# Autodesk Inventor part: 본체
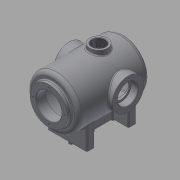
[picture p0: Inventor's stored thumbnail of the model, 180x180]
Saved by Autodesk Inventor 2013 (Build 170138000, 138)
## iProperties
Created: 2016-02
Part Number: 본체
Material: 일반
Document SubType Name: Modeling
Designer: mduedu
Density: 2.71 g/cm^3
Author: mduedu
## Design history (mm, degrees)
sketch "스케치2"
  geometry: L1 (0, 100)-(0, -100); L2 (65, -75.993)-(65, 100); L3 (65, 100)-(0, 100); A1 r 100 centre (0, 0) between (0, -100) and (65, -75.993); 2 further points
  constraints: 6 end point, 2 midpoint, 2 point on circle, 1 centre point, 1 coincident, 1 horizontal, 1 parallel, 1 vertical
  dimensions: "d3" = 200 distance of L1.start L1.end; "d5" = 130 diameter of L2 L1; "d6" = 100 radius of A1
revolve "회전1" sketch "스케치2" stored, may be unused: angle "d7" = 90 deg
sketch "스케치3"
  geometry: C1 r 47.5 at (0, 0); 1 further point
  constraints: 1 centre point, 1 coincident
  dimensions: "d8" = 95 diameter of C1
extrude "돌출2" join sketch "스케치3" distance "d10" = 10; taper "d11" = 0 deg
sketch "스케치5"
  geometry: L1 (47.5, 110)-(47.5, 100) reference; L2 (47.5, 100)-(65, 100) reference; L3 (65, 100)-(65, -75.993) reference; L4 (-65, -75.993)-(-65, 100) reference; L5 (-65, 100)-(-47.5, 100) reference; L6 (-47.5, 100)-(-47.5, 110) reference; L7 (-47.5, 110)-(47.5, 110) reference; L8 (55, 85)-(55, -71.239); L9 (0, 85)-(55, 85); L10 (0, 85)-(0, -90); A1 r 100 centre (0, 0) between (0, -100) and (65, -75.993) reference; A2 r 100 centre (0, 0) between (-65, -75.993) and (0, -100) reference; A3 r 90 centre (0, 0) between (0, -90) and (55, -71.239); 1 further point
  constraints: 6 end point, 2 point on circle, 1 centre point, 1 parallel, 1 perpendicular, 1 point on line, 1 vertical
  dimensions: "d13" = 10 distance between parallel lines of L3 L8; "d14" = 10 radial gap between concentric circles of A3 A1; "d15" = 15 distance between parallel lines of L9 L2
revolve "회전2" sketch "스케치5" stored, may be unused: angle "d16" = 90 deg
hole "구멍1" diameter "d19" = 65; stored, may be unused: countersink angle "d23" = 90 deg, drill point angle "d25" = 118 deg; dims "d17" = 10, "d18" = 10, "d20" = 6, "d21" = 4, "d22" = 2, "d24" = 8
node "작업 평면1"
sketch "스케치6"
  geometry: L1 (47.5, 110)-(-47.5, 110) reference; C1 r 40 at (0, -17); 1 further point
  constraints: 1 centre point, 1 vertical alignment
  dimensions: "d27" = 80 diameter of C1; "d29" = 127 distance from line of C1.centre L1
extrude "돌출3" join sketch "스케치6" stored distance "d30" = 10; taper "d31" = 0 deg
hole "구멍2" diameter "d34" = 42; stored, may be unused: countersink angle "d38" = 90 deg, drill point angle "d40" = 118 deg; dims "d32" = 10, "d33" = 10, "d35" = 6, "d36" = 52, "d37" = 18, "d39" = 8
sketch "스케치7" dims "d41" = 65
  geometry: C1 r 40 at (0, 0) reference; 3 further points
  constraints: 2 vertical alignment, 1 coincident, 2 other
hole "구멍3" sketch "스케치7" at (0, 32.5) diameter "d43" = 3.242; stored, may be unused: countersink angle "d47" = 90 deg, drill point angle "d49" = 118 deg; dims "d44" = 11, "d45" = 13, "d46" = 18, "d48" = 13
sketch "스케치8" dims "d53" = 80
  geometry: 3 further points
  constraints: 2 vertical alignment, 1 coincident, 2 other
hole "구멍4" sketch "스케치8" at (0, 40) diameter "d56" = 3.242; stored, may be unused: countersink angle "d60" = 90 deg, drill point angle "d62" = 118 deg; dims "d57" = 11, "d58" = 13, "d59" = 18, "d61" = 13
fillet "모깎기1" dims "d66" = 10
fillet "모깎기2" dims "d67" = 3
fillet "모깎기3" dims "d68" = 0.3
chamfer "모따기1" distance "d69" = 1; stored, may be unused: second distance "d70" = 2, angle "d71" = 45 deg
node "작업 평면5"
sketch "스케치10"
  geometry: L1 (-50, -63)-(50, -63); L2 (50, -63)-(50, -43); L3 (50, -43)-(-50, -43); L4 (-50, -43)-(-50, -63); L5 (-50, 0)-(50, 0); L6 (-50, 63)-(50, 63); L7 (50, 63)-(50, 43); L8 (50, 43)-(-50, 43); L9 (-50, 43)-(-50, 63); 2 further points
  constraints: 18 end point, 4 symmetric about line, 2 parallel, 2 perpendicular, 1 coincident, 1 horizontal, 1 midpoint
  dimensions: "d80" = 20 distance of L3.end L1.start; "d82" = 100 distance of L1.start L1.end; "d130" = 43 vertical distance of L3.end point (0, 0); "d131" = 50 horizontal distance of L3.end point (0, 0); "d132" = 100 distance of L5.start L5.end
extrude "돌출5" join sketch "스케치10" stored distance "d84" = 10; taper "d85" = 0 deg
sketch "스케치11"
  geometry: L1 (-100, -43)-(-100, 43); L2 (-65, 90)-(-65, -71.239) reference; L3 (-100, -43)-(-41.533, -43) reference; L4 (-100, 43)-(-41.533, 43) reference; 1 further point
  constraints: 2 end point, 1 point on line, 1 vertical
feature "리브1" sketch "스케치11" dims "d88" = 1, "d89" = 20, "d90" = 0, "d91" = 0, "d92" = 1, "d93" = 1
fillet "모깎기18" dims "d179" = 3
fillet "모깎기19" dims "d180" = 3
fillet "모깎기20" dims "d181" = 3
fillet "모깎기21" dims "d182" = 3
fillet "모깎기16" dims "d167" = 3
fillet "모깎기17" dims "d168" = 3
node "작업 평면6"
sketch "스케치19"
  geometry: L1 (75, -57)-(75, 23) reference; L2 (-75, -57)-(-75, 23) reference; L3 (75, -17)-(-75, -17); C1 r 22.5 at (0, -17); 1 further point
  constraints: 3 midpoint, 2 end point, 1 centre point
  dimensions: "d149" = 45 diameter of C1
extrude "돌출11" join sketch "스케치19" stored distance "d150" = 10; taper "d151" = 0 deg
hole "구멍6" diameter "d154" = 33.376; stored, may be unused: countersink angle "d158" = 90 deg, drill point angle "d160" = 118 deg; dims "d155" = 6, "d156" = 4, "d157" = 2, "d159" = 8, "d177" = 10, "d178" = 10
fillet "모깎기11" dims "d161" = 3
chamfer "모따기3" distance "d164" = 1; stored, may be unused: second distance "d165" = 2, angle "d166" = 45 deg
sketch "스케치20"
  geometry: L1 (10, 40)-(10, -40) reference; L2 (13, -43)-(47, -43) reference; L3 (-10, -40)-(-10, 40) reference; L4 (47, 43)-(13, 43) reference; L5 (-40, 53)-(40, 53); L6 (-40, -53)-(40, -53); L7 (0, 53)-(0, -53); L8 (50, -46)-(50, -60) reference; L9 (47, -63)-(-47, -63) reference; L10 (-50, -60)-(-50, -46) reference; L11 (-47, -43)-(-13, -43) reference; L12 (-13, 43)-(-47, 43) reference; L13 (-50, 46)-(-50, 60) reference; L14 (-47, 63)-(47, 63) reference; L15 (50, 60)-(50, 46) reference; C1 r 5 at (0, 53); C2 r 5 at (0, 0); C3 r 5 at (0, -53); A1 r 3 centre (13, -40) between (10, -40) and (13, -43) reference; A2 r 3 centre (-13, -40) between (-13, -43) and (-10, -40) reference; A3 r 3 centre (-13, 40) between (-10, 40) and (-13, 43) reference; A4 r 3 centre (13, 40) between (13, 43) and (10, 40) reference; A5 r 3 centre (47, -46) between (50, -46) and (47, -43) reference; A6 r 3 centre (47, -60) between (47, -63) and (50, -60) reference; A7 r 3 centre (-47, -60) between (-50, -60) and (-47, -63) reference; A8 r 3 centre (-47, -46) between (-47, -43) and (-50, -46) reference; A9 r 3 centre (-47, 46) between (-50, 46) and (-47, 43) reference; A10 r 3 centre (-47, 60) between (-47, 63) and (-50, 60) reference; A11 r 3 centre (47, 60) between (50, 60) and (47, 63) reference; A12 r 3 centre (47, 46) between (47, 43) and (50, 46) reference; 1 further point
  constraints: 6 end point, 3 centre point, 3 coincident, 2 midpoint, 2 parallel
  dimensions: "d169" = 10 diameter of C1; "d170" = 10 diameter of C2; "d171" = 10 diameter of C3
extrude "돌출12" join sketch "스케치20" distance "d172" = 10; taper "d173" = 0 deg
chamfer "모따기4" distance "d174" = 1; stored, may be unused: second distance "d175" = 2, angle "d176" = 45 deg
node "솔리드2"
pattern_circular "원형 패턴1" dims angle "d51" = 360 deg
mirror "대칭1"
pattern_circular "원형 패턴2" dims angle "d64" = 360 deg
node "절단 모서리 투영1"
node "절단 모서리 투영4"
other parameters: "d26" = 75, "d136" = 175
